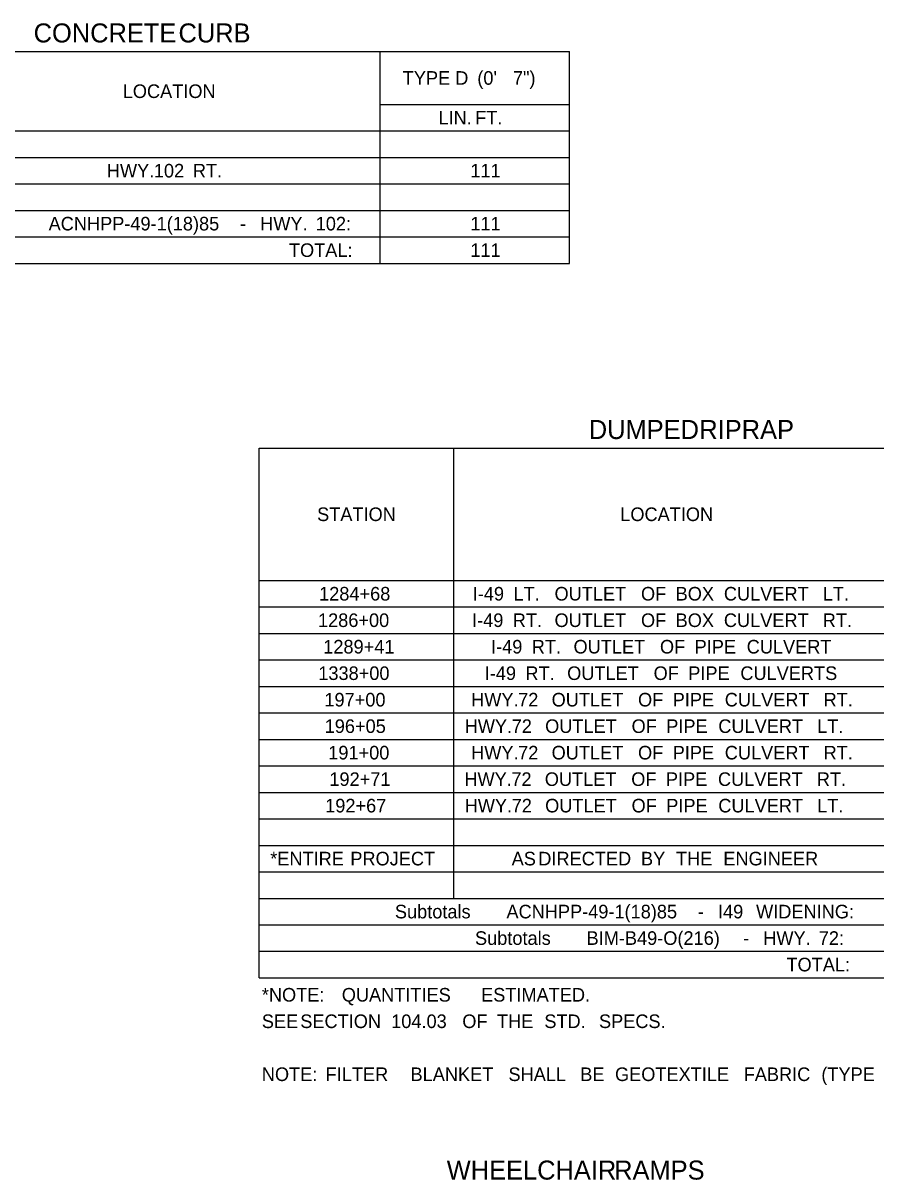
# Model space of a CAD drawing. Extents: x 1226605 to 1228152, y 151309 to 152316.
# Drawn here: x 1227620.6 to 1227934.5, y 151834.3 to 152260 of the extents above; entities that cross this region are included whole.
import ezdxf

# ---------------------------------------------------------------- set-up
doc = ezdxf.new("R2010")
doc.units = 0
doc.layers.add('R_Dimension', color=7, linetype='Continuous')

msp = doc.modelspace()

# ---------------------------------------------------------------- linework, layer by layer
at = {"layer": 'R_Dimension'}
for p, q in [((1227509.27, 152249.62), (1227821.75, 152249.62)), ((1227752.04, 152171.62), (1227752.04, 152249.62)), ((1227821.75, 152171.62), (1227821.75, 152249.62)), ((1227752.04, 152230.12), (1227821.75, 152230.12)), ((1227509.27, 152220.37), (1227821.75, 152220.37)), ((1227509.27, 152210.62), (1227821.75, 152210.62)), ((1227509.27, 152200.87), (1227821.75, 152200.87)), ((1227509.27, 152191.12), (1227821.75, 152191.12)), ((1227509.27, 152181.37), (1227821.75, 152181.37)), ((1227509.27, 152171.62), (1227821.75, 152171.62)), ((1227707.52, 152103.65), (1228035.61, 152103.65)), ((1227707.52, 151908.65), (1227707.52, 152103.65)), ((1227779.18, 151937.9), (1227779.18, 152103.65)), ((1227707.52, 152054.9), (1228035.61, 152054.9)), ((1227707.52, 152045.15), (1228035.61, 152045.15)), ((1227707.52, 152035.4), (1228035.61, 152035.4)), ((1227707.52, 152025.65), (1228035.61, 152025.65)), ((1227707.52, 152015.9), (1228035.61, 152015.9)), ((1227707.52, 152006.15), (1228035.61, 152006.15)), ((1227707.52, 151996.4), (1228035.61, 151996.4)), ((1227707.52, 151986.65), (1228035.61, 151986.65)), ((1227707.52, 151976.9), (1228035.61, 151976.9)), ((1227707.52, 151967.15), (1228035.61, 151967.15)), ((1227707.52, 151957.4), (1228035.61, 151957.4)), ((1227707.52, 151947.65), (1228035.61, 151947.65)), ((1227707.52, 151937.9), (1228035.61, 151937.9)), ((1227707.52, 151928.15), (1228035.61, 151928.15)), ((1227707.52, 151918.4), (1228035.61, 151918.4)), ((1227707.52, 151908.65), (1228035.61, 151908.65))]:
    msp.add_line(p, q, dxfattribs=at)

# ---------------------------------------------------------------- texts
for s, height, p in [('CONCRETE', 7, (1227624.5, 152252.94)), (' CURB', 7, (1227675.21, 152252.94)), ('TYPE', 5, (1227760.36, 152237.37)), (' D', 5, (1227777.84, 152237.37)), (" (0'", 5, (1227785.95, 152237.37)), (' 7")', 5, (1227799.06, 152237.37)), ('LOCATION', 5, (1227657.29, 152232.49)), ('LIN.', 5, (1227773.49, 152222.74)), (' FT.', 5, (1227785.15, 152222.74)), ('HWY.', 5, (1227651.44, 152203.24)), (' 102', 5, (1227666.88, 152203.24)), (' RT.', 5, (1227681.25, 152203.24)), ('111', 5, (1227785.24, 152203.24)), (' ACNHPP-49-1(18)85', 5, (1227628.15, 152183.74)), (' -', 5, (1227698.58, 152183.74)), (' HWY.', 5, (1227706.02, 152183.74)), (' 102:', 5, (1227726.46, 152183.74)), ('111', 5, (1227785.24, 152183.74)), ('TOTAL:', 5, (1227718.46, 152173.99)), ('111', 5, (1227785.24, 152173.99)), ('DUMPED', 7, (1227828.84, 152106.97)), (' RIPRAP', 7, (1227866.93, 152106.97)), ('STATION', 5, (1227728.84, 152076.77)), ('LOCATION', 5, (1227840.43, 152076.77)), ('1284+68', 5, (1227729.57, 152047.52)), ('I-49', 5, (1227786.12, 152047.52)), (' LT.', 5, (1227799.23, 152047.52)), (' OUTLET', 5, (1227814.38, 152047.52)), (' OF', 5, (1227846.2, 152047.52)), (' BOX', 5, (1227858.95, 152047.52)), (' CULVERT', 5, (1227876.71, 152047.52)), (' LT.', 5, (1227913.09, 152047.52)), ('1286+00', 5, (1227729.16, 152037.77)), ('I-49', 5, (1227785.88, 152037.77)), (' RT.', 5, (1227798.99, 152037.77)), (' OUTLET', 5, (1227814.38, 152037.77)), (' OF', 5, (1227846.2, 152037.77)), (' BOX', 5, (1227858.95, 152037.77)), (' CULVERT', 5, (1227876.71, 152037.77)), (' RT.', 5, (1227913.09, 152037.77)), ('1289+41', 5, (1227731.1, 152028.02)), ('I-49', 5, (1227792.87, 152028.02)), (' RT.', 5, (1227805.98, 152028.02)), (' OUTLET', 5, (1227821.37, 152028.02)), (' OF', 5, (1227853.18, 152028.02)), (' PIPE', 5, (1227865.94, 152028.02)), (' CULVERT', 5, (1227885.11, 152028.02)), ('1338+00', 5, (1227729.27, 152018.27)), ('I-49', 5, (1227790.53, 152018.27)), (' RT.', 5, (1227803.64, 152018.27)), (' OUTLET', 5, (1227819.03, 152018.27)), (' OF', 5, (1227850.84, 152018.27)), (' PIPE', 5, (1227863.6, 152018.27)), (' CULVERTS', 5, (1227882.77, 152018.27)), ('197+00', 5, (1227731.52, 152008.52)), ('HWY.', 5, (1227785.55, 152008.52)), (' 72', 5, (1227800.98, 152008.52)), (' OUTLET', 5, (1227813.3, 152008.52)), (' OF', 5, (1227845.11, 152008.52)), (' PIPE', 5, (1227857.87, 152008.52)), (' CULVERT', 5, (1227877.04, 152008.52)), (' RT.', 5, (1227913.42, 152008.52)), ('196+05', 5, (1227731.62, 151998.77)), ('HWY.', 5, (1227783.16, 151998.77)), (' 72', 5, (1227798.6, 151998.77)), (' OUTLET', 5, (1227810.92, 151998.77)), (' OF', 5, (1227842.73, 151998.77)), (' PIPE', 5, (1227855.49, 151998.77)), (' CULVERT', 5, (1227874.66, 151998.77)), (' LT.', 5, (1227911.04, 151998.77)), ('191+00', 5, (1227732.94, 151989.02)), ('HWY.', 5, (1227785.55, 151989.02)), (' 72', 5, (1227800.98, 151989.02)), (' OUTLET', 5, (1227813.3, 151989.02)), (' OF', 5, (1227845.11, 151989.02)), (' PIPE', 5, (1227857.87, 151989.02)), (' CULVERT', 5, (1227877.04, 151989.02)), (' RT.', 5, (1227913.42, 151989.02)), ('192+71', 5, (1227733.35, 151979.27)), ('HWY.', 5, (1227783.05, 151979.27)), (' 72', 5, (1227798.48, 151979.27)), (' OUTLET', 5, (1227810.8, 151979.27)), (' OF', 5, (1227842.61, 151979.27)), (' PIPE', 5, (1227855.37, 151979.27)), (' CULVERT', 5, (1227874.54, 151979.27)), (' RT.', 5, (1227910.92, 151979.27)), ('192+67', 5, (1227731.81, 151969.52)), ('HWY.', 5, (1227783.16, 151969.52)), (' 72', 5, (1227798.6, 151969.52)), (' OUTLET', 5, (1227810.92, 151969.52)), (' OF', 5, (1227842.73, 151969.52)), (' PIPE', 5, (1227855.49, 151969.52)), (' CULVERT', 5, (1227874.66, 151969.52)), (' LT.', 5, (1227911.04, 151969.52)), ('*ENTIRE', 5, (1227711.58, 151950.02)), (' PROJECT', 5, (1227739.21, 151950.02)), ('AS', 5, (1227800.45, 151950.02)), (' DIRECTED', 5, (1227808.4, 151950.02)), (' BY', 5, (1227846.2, 151950.02)), (' THE', 5, (1227859.07, 151950.02)), (' ENGINEER', 5, (1227876.51, 151950.02)), ('Subtotals', 5, (1227757.47, 151930.52)), (' ACNHPP-49-1(18)85', 5, (1227796.68, 151930.52)), (' I49', 5, (1227874.55, 151930.52)), (' WIDENING:', 5, (1227888.57, 151930.52)), (' -', 5, (1227867.11, 151930.52)), ('Subtotals', 5, (1227786.96, 151920.77)), (' BIM-B49-O(216)', 5, (1227826.17, 151920.77)), (' 72:', 5, (1227911.64, 151920.77)), (' -', 5, (1227883.77, 151920.77)), (' HWY.', 5, (1227891.21, 151920.77)), ('TOTAL:', 5, (1227901.6, 151911.02)), ('*NOTE:', 5, (1227708.49, 151899.9)), ('   QUANTITIES', 5, (1227732.35, 151899.9)), (' ESTIMATED.', 5, (1227787.35, 151899.9)), ('SEE', 5, (1227708.49, 151890.15)), (' SECTION', 5, (1227720.78, 151890.15)), (' 104.03', 5, (1227754.24, 151890.15)), (' OF', 5, (1227780.42, 151890.15)), (' THE', 5, (1227793.18, 151890.15)), (' STD.', 5, (1227810.62, 151890.15)), (' SPECS.', 5, (1227830.74, 151890.15)), ('NOTE:', 5, (1227708.49, 151870.65)), ('  FILTER', 5, (1227728.26, 151870.65)), (' BLANKET', 5, (1227761.37, 151870.65)), (' SHALL', 5, (1227797.43, 151870.65)), (' BE', 5, (1227823.85, 151870.65)), (' GEOTEXTILE', 5, (1227836.64, 151870.65)), (' FABRIC', 5, (1227884, 151870.65)), (' (TYPE', 5, (1227912.59, 151870.65)), ('WHEELCHAIR', 7, (1227776.55, 151834.37)), (' RAMPS', 7, (1227835.58, 151834.37))]:
    msp.add_text(s, height=height, dxfattribs=at).set_placement(p)

doc.saveas('drawing.dxf')
